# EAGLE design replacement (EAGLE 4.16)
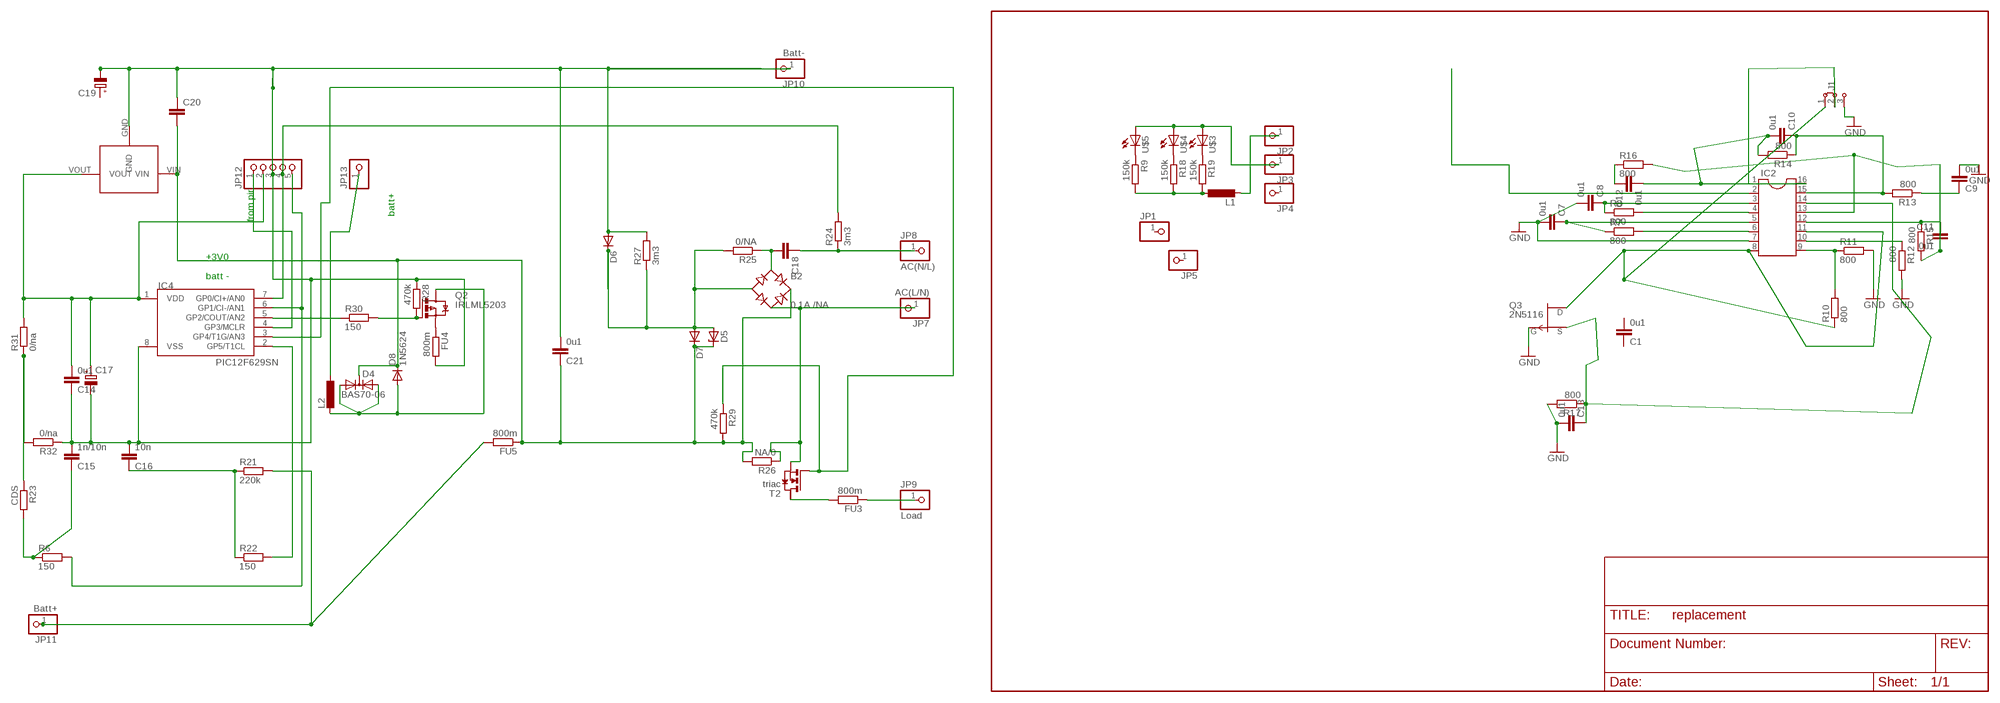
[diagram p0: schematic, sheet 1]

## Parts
B2  0.1A /NA  RECTIFIER-B40S  [B40S]
C1  0u1  C-EUC1206  [C1206]
C7  0u1  C-EUC1206  [C1206]
C8  0u1  C-EUC1206  [C1206]
C9  0u1  C-EUC1206  [C1206]
C10  0u1  C-EUC1206  [C1206]
C11  0u1  C-EUC1206  [C1206]
C12  0u1  C-EUC1206  [C1206]
C13  0u1  C-EUC1206  [C1206]
C14  0u1  C-EUC1206  [C1206]
C15  1n/10n  C-EUC1206  [C1206]
C16  10n  C-EUC1206  [C1206]
C17  CPOL-EUE2.5-6  [E2,5-6]
C18  C-EU050-025X075  [C050-025X075]
C19  CPOL-EUE2,5-6E  [E2,5-6E]
C20  C-EUC0805  [C0805]
C21  0u1  C-EUC1206  [C1206]
D4  BAS70-06  [SOT23]
D5  ZENER-DIODESOT23  [SOT23]
D6  DIODE-MELF-MLL41  [MELF-MLL41]
D7  DIODE-MINIMELF  [MINIMELF]
D8  1N5624  [DO201-15]
FU3  800m  R-EU_0204/5  [0204/5]
FU4  800m  R-EU_0204/5  [0204/5]
FU5  800m  R-EU_0204/5  [0204/5]
IC2  DIL16  [DIL16]
IC4  PIC12F629SN  [SO-08]
J1  J2X2MM  [04C]
JP1  PINHD-1X1  [1X01]
JP2  PINHD-1X1  [1X01]
JP3  PINHD-1X1  [1X01]
JP4  PINHD-1X1  [1X01]
JP5  PINHD-1X1  [1X01]
JP7  AC(L/N)  PINHD-1X1  [1X01]
JP8  AC(N/L)  PINHD-1X1  [1X01]
JP9  Load  PINHD-1X1  [1X01]
JP10  Batt-  PINHD-1X1  [1X01]
JP11  Batt+  PINHD-1X1  [1X01]
JP12  PINHD-1X5  [1X05]
JP13  PINHD-1X1  [1X01]
L1  L-EU0207/7  [0207/7]
L2  L-EU2200-15.24  [2200-15.24]
Q2  IRLML5203  [MICRO3]
Q3  2N5116  [TO18]
R6  150  R-EU_R0805  [R0805]
R7  800  R-EU_R1206  [R1206]
R8  800  R-EU_R1206  [R1206]
R9  150k  R-EU_R1206  [R1206]
R10  800  R-EU_R1206  [R1206]
R11  800  R-EU_R1206  [R1206]
R12  800  R-EU_R1206  [R1206]
R13  800  R-EU_R1206  [R1206]
R14  800  R-EU_R1206  [R1206]
R15  800  R-EU_R1206  [R1206]
R16  800  R-EU_R1206  [R1206]
R17  800  R-EU_R1206  [R1206]
R18  150k  R-EU_R1206  [R1206]
R19  150k  R-EU_R1206  [R1206]
R21  220k  R-EU_R0805  [R0805]
R22  150  R-EU_R0805  [R0805]
R23  CDS  R-EU_0411/3V  [0411V]
R24  3m3  R-EU_R1206  [R1206]
R25  0/NA  R-EU_R0402  [R0402]
R26  NA/0  R-EU_R0402  [R0402]
R27  3m3  R-EU_R1206  [R1206]
R28  470k  R-EU_R0805  [R0805]
R29  470k  R-EU_R0805  [R0805]
R30  150  R-EU_R0805  [R0805]
R31  0/na  R-EU_R0402  [R0402]
R32  0/na  R-EU_R0402  [R0402]
T2  triac  NMOSSOT223  [SOT223]
U$1  VREG-S  [TO92-S]
U$3  LED5MM  [LED5MM]
U$4  LED5MM  [LED5MM]
U$5  LED5MM  [LED5MM]

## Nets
GND: C7.2 C8.2 C9.2 C13.2 C14.1 C15.2 C16.2 C17.- C19.- C20.1 C21.2 D6.A FU4.2 IC2.7 IC4.8(VSS) J1.3 JP10.1 JP12.3 Q3.2(G) R11.2 R12.2 R17.2 R27.2 R28.1 R32.1 U$1.GND
N$8: C15.1 R6.1 R23.2
N$10: C16.1 R21.1 R22.1
N$11: JP2.1 L1.2
N$15: IC4.4(GP3/MCLR) JP12.1
N$17: IC2.2
N$19: D4.1(A1) D4.2(A2) D8.A L2.2 Q2.3(D)
N$20: C18.1 JP8.1 R24.1
N$21: FU3.1 JP9.1
N$22: FU3.2 T2.2(D)
N$24: B2.AC2 JP7.1 R26.1 T2.3(S)
N$25: B2.- D5.1(A) D6.C D7.A R25.2 R27.1
N$26: B2.AC1 C18.2 R25.1
N$27: IC4.7(GP0/CI+/AN0) JP12.4 R24.2
N$28: JP13.1 L2.1
N$31: FU4.1 Q2.2(S)
N$32: JP3.1 U$3.A U$4.A U$5.A
N$34: IC2.8 IC2.11 J1.1 Q3.3(D) R10.1
N$38: R9.1 U$5.K(C)
N$39: IC2.1 J1.2
N$40: C8.1 IC2.3 R8.1
N$41: IC2.6 R7.2
N$42: IC2.4 R8.2
N$43: C7.1 IC2.5 R7.1
N$44: IC2.10 R12.1
N$45: IC2.9 R10.2 R11.1
N$46: C9.1 R13.1
N$47: C10.1 IC2.15 R13.2 R14.1
N$48: C11.1 IC2.12 R15.1
N$49: C12.1 R16.1
N$50: C13.1 IC2.14 Q3.1(S) R17.1
N$51: C11.2 IC2.13 R15.2 R16.2
N$52: FU5.2 JP11.1 R21.2
N$53: C10.2 C12.2 IC2.16 R14.2
N$54: R18.1 U$4.K(C)
N$55: R19.1 U$3.K(C)
N$56: IC4.3(GP4/T1G/AN3) R29.1 T2.1(G)
N$58: L1.1 R9.2 R18.2 R19.2
N$59: Q2.1(G) R28.2 R30.2
N$60: IC4.5(GP2/COUT/AN2) R30.1
N$61: IC4.6(GP1/CI-/AN1) JP12.5 R6.2
N$62: IC4.2(GP5/T1CL) R22.2
N$63: R23.1 R31.1 R32.2
N$64: C14.2 C17.+ IC4.1(VDD) JP12.2 R31.2 U$1.VOUT
N$65: B2.+ C20.2 C21.1 D4.3(C) D5.3(C) D7.C D8.C FU5.1 R26.2 R29.2 U$1.VIN
Unconnected: C1.1 C1.2 C19.+ JP1.1 JP4.1 JP5.1 T2.4(D2)

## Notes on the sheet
- batt+
- from pir
- +3V0
- batt -

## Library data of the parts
B2 = rectifier:RECTIFIER-: Rectifier
C1 C7-C16 C18 C21 = rcl:C-EU: CAPACITOR, European symbol
C17 C19 = rcl(2):CPOL-EU: POLARIZED CAPACITOR, European symbol
C20 = rcl(2):C-EU: CAPACITOR, European symbol
D4 = diode-1:BAS70-06: Silicon Schottky Diodes General-purpose diode for high-speed switching
D5 = diode-1:ZENER-DIODE: Z-Diode
D6 D7 = diode-1:DIODE-: DIODE
D8 = diode:1N5624: DIODE
FU3-FU5 R6-R19 R21-R32 = rcl:R-EU_: RESISTOR, European symbol
IC2 = ic-package:DIL16: Dual In Line
IC4 = microchip-3:PIC12F6*: uPC nW 1k Program Flash memory 2x Timer Comparator 10b A/D converter/ 4xIN
J1 = jumper:J2: Jumper switch 2 x 2.5 mm
JP1-JP5 JP7-JP11 = pinhead:PINHD-1X1: PIN HEADER
JP12 = pinhead(2):PINHD-1X5: PIN HEADER
JP13 = pinhead(2):PINHD-1X1: PIN HEADER
L1 L2 = rcl:L-EU: INDUCTOR, European symbol
Q2 = transistor-power:IRLML5203: HEXFET P-Channel Power MOSFET
Q3 = transistor-fet:2N5116: P-Channel Junction FET Source: Vishay 70260.pdf
T2 = zetex:NMOSSOT223: MOS FET
U$1 = spoton:VREG-S: vreg aus spoton
U$3-U$5 = led(3):LED: LED

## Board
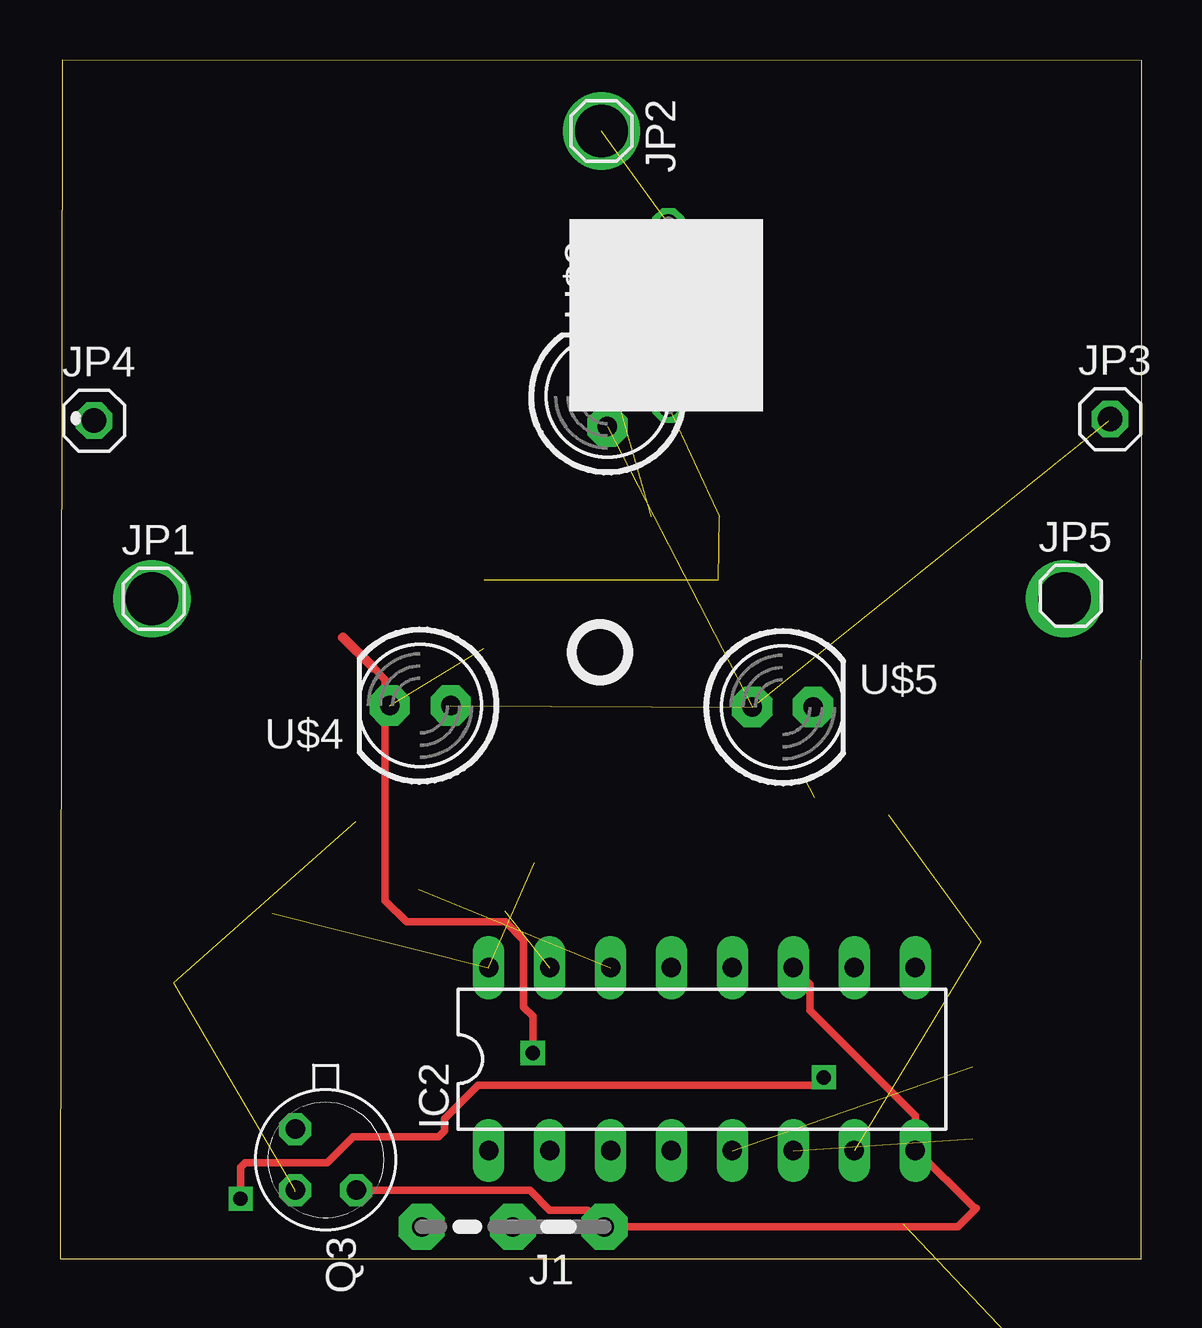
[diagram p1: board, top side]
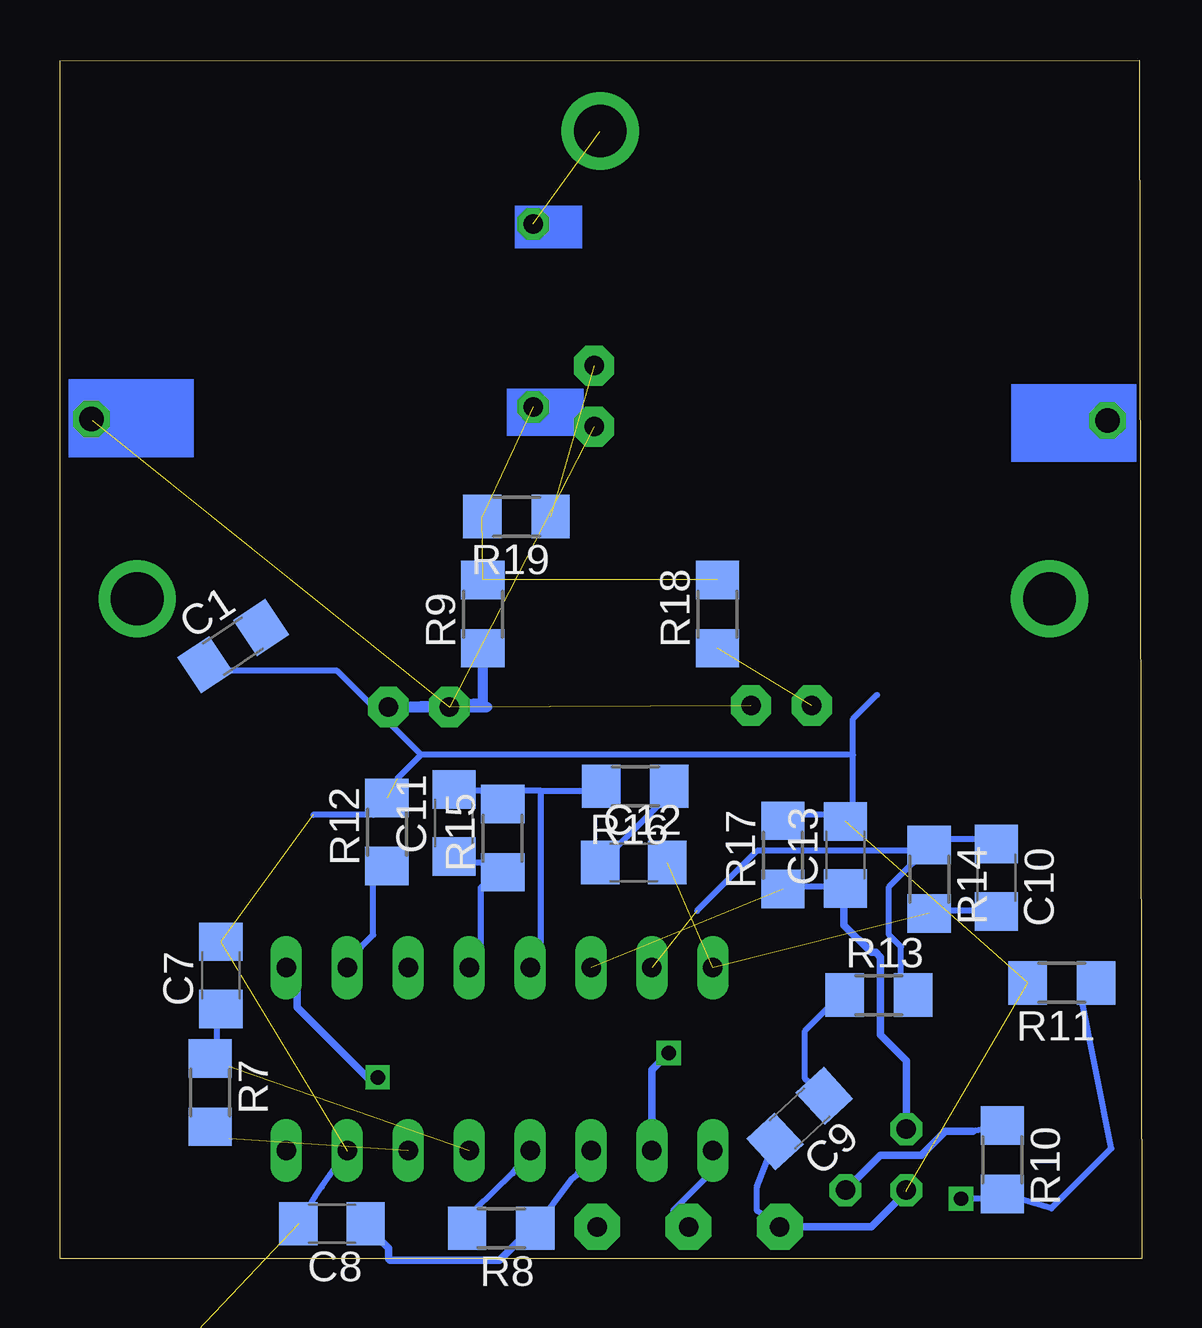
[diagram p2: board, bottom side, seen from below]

Size 45.09 x 49.94 mm. Coordinates in mm from the lower left corner, seen from the top.
Outline: 0,0 45.07,0 45.08,49.91 0.09,49.94 0,0
Copper layers (1*16): Top 0.035mm / dielectric 1.5mm / Bottom 0.035mm
Design rules "default": minimum track width 10mil, minimum drill 24mil, track to track 8mil, track to pad 8mil, pad to pad 8mil, via to via 8mil, smd to smd 8mil, copper to edge 40mil, drill to drill 8mil, minimum pad ring 10mil, minimum via ring 8mil, stop-mask expansion 4mil, vias tented up to drill 0mil, thermal gap 10mil

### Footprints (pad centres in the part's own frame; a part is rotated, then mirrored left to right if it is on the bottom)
B40S = smd 1.5 x 1.7: + -2.55,-4.5; - 2.55,-4.5; AC1 -2.55,4.5; AC2 2.55,4.5
C1206 = smd 1.6 x 1.8: 1 -1.4,0; 2 1.4,0
E2,5-6 = drill 0.813 pad 1.6 round: + -1.27,0 | drill 0.813 pad 1.6 octagon: - 1.27,0
C050-025X075 = drill 0.813 octagon: 1 -2.54,0; 2 2.54,0
E2,5-6E = drill 0.813 pad 1.575 round: + -1.27,0 | drill 0.813 pad 1.575 octagon: - 1.27,0
C0805 = smd 1.3 x 1.5: 1 -0.95,0; 2 0.95,0
SOT23 = smd 1 x 1.4: 1 -0.95,-1.1; 2 0.95,-1.1; 3 0,1.1
MELF-MLL41 = smd 2.5 x 3: A 2.625,0; C -2.625,0
MINIMELF = smd 1.4 x 1.8: A 1.7,0; C -1.7,0
DO201-15 = drill 1.499 long: A 7.62,0; C -7.62,0
0204/5 = drill 0.813 octagon: 1 -2.54,0; 2 2.54,0
DIL16 = drill 0.813 long: 1 -8.89,-3.81; 2 -6.35,-3.81; 3 -3.81,-3.81; 4 -1.27,-3.81; 5 1.27,-3.81; 6 3.81,-3.81; 7 6.35,-3.81; 8 8.89,-3.81; 9 8.89,3.81; 10 6.35,3.81; 11 3.81,3.81; 12 1.27,3.81; 13 -1.27,3.81; 14 -3.81,3.81; 15 -6.35,3.81; 16 -8.89,3.81
SO-08 = smd 0.6 x 2.2: 1 -1.905,-2.6; 2 -0.635,-2.6; 3 0.635,-2.6; 4 1.905,-2.6; 5 1.905,2.6; 6 0.635,2.6; 7 -0.635,2.6; 8 -1.905,2.6
04C = drill 0.813 pad 1.905 octagon: 1 -1.905,0; 2 1.905,0; 3 5.715,0
1X01 = drill 1.016 octagon: 1 0,0
1X05 = drill 1.016 square: 1 -5.08,0 | drill 1.016 octagon: 2 -2.54,0; 3 0,0; 4 2.54,0; 5 5.08,0
1X01' = drill 1.016 square: 1 0,0
0207/7 = drill 0.813 octagon: 1 -3.81,0; 2 3.81,0
2200-15.24 = drill 0.8 pad 1.27 round: 1 -7.62,0; 2 7.62,0
MICRO3 = smd 0.8 x 0.9: 1 -0.95,-1; 2 0.95,-1; 3 0,1
TO18 = drill 0.813 octagon: 1 -1.27,-1.27; 2 1.27,-1.27; 3 1.27,1.27
R0805 = smd 1.3 x 1.5: 1 -0.85,0; 2 0.85,0
R1206 = smd 1.6 x 1.803: 1 -1.422,0; 2 1.422,0
0411V = drill 0.914 octagon: 1 -2.54,0; 2 1.27,0
R0402 = smd 0.7 x 0.9: 1 -0.65,0; 2 0.65,0
SOT223 = smd 1.219 x 2.235: 1 -2.311,-3.099; 2 0,-3.099; 3 2.311,-3.099 | smd 3.6 x 2.2: 4 0,3.099
TO92-S = drill 0.6 round: GND -2.54,0; VOUT 0,0 | drill 0.6 offset: VIN -1.27,1.27
LED5MM = drill 0.813 pad 1.676 octagon: A -1.27,0; K 1.27,0

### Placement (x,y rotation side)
B2  not placed on the board
C1  37.87,25.52 33.7 bottom
C7  38.38,11.81 90 bottom
C8  33.74,1.46 180 bottom
C9  14.25,5.84 222.8 bottom
C10  6.06,15.87 270 bottom
C11  28.66,18.16 90 bottom
C12  21.17,16.51 0 bottom
C13  12.34,16.82 90 bottom
C14  not placed on the board
C15  not placed on the board
C16  not placed on the board
C17  not placed on the board
C18  not placed on the board
C19  not placed on the board
C20  not placed on the board
C21  not placed on the board
D4  not placed on the board
D5  not placed on the board
D6  not placed on the board
D7  not placed on the board
D8  not placed on the board
FU3  not placed on the board
FU4  not placed on the board
FU5  not placed on the board
IC2  26.76,8.31 0 top
IC4  not placed on the board
J1  20.79,1.33 180 top
JP1  3.9,27.49 0 top
JP2  22.57,46.98 270 top
JP3  43.78,34.98 0 top
JP4  1.42,34.92 0 top
JP5  42.13,27.62 0 top
JP7  not placed on the board
JP8  not placed on the board
JP9  not placed on the board
JP10  not placed on the board
JP11  not placed on the board
JP12  not placed on the board
JP13  [1X01']  not placed on the board
L1  25.36,39.3 90 top
L2  not placed on the board
Q2  not placed on the board
Q3  11.07,4.12 270 top
R6  not placed on the board
R7  38.82,6.92 270 bottom
R8  26.7,1.27 180 bottom
R9  27.46,26.86 90 bottom
R10  5.8,4.12 270 bottom
R11  3.33,11.49 180 bottom
R12  31.46,17.78 90 bottom
R13  10.95,10.98 0 bottom
R14  8.85,15.81 270 bottom
R15  26.63,17.52 90 bottom
R16  21.11,19.68 180 bottom
R17  14.95,16.82 90 bottom
R18  17.68,26.86 90 bottom
R19  26.06,30.92 180 bottom
R21  not placed on the board
R22  not placed on the board
R23  not placed on the board
R24  not placed on the board
R25  not placed on the board
R26  not placed on the board
R27  not placed on the board
R28  not placed on the board
R29  not placed on the board
R30  not placed on the board
R31  not placed on the board
R32  not placed on the board
T2  not placed on the board
U$1  not placed on the board
U$3  22.82,35.94 90 top
U$4  15.01,23.05 180 top
U$5  30.12,22.98 0 top

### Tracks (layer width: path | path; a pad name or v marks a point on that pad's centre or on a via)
GND  (22 unrouted)
  Bottom 0.254: R17.2 14.53,18.5 13.03,18.5 C13.2 12.03,19 12.03,21 | 12.03,21 12.03,22.5 11.03,23.5 | 30.03,21 31.03,20 | 12.03,21 30.03,21 | 38.03,24.5 33.53,24.5 30.03,21 | 34.53,18.5 32.03,18.5 R12.2 | C9.2 16.03,3 16.03,2 J1.3 | C8.2 34.43,2.61 34.18,2.99 IC2.7
  Bottom 0.305: J1.3 11.26,1.33 9.8,2.79
N$2  (via drill 2.2)
  other vias: 3.84,27.49
N$3  (via drill 2.2)
  other vias: 41.87,27.49
N$5  (via drill 2.2)
  other vias: 22.57,46.98
N$8  (2 unrouted)
N$10  (2 unrouted)
N$11  (1 unrouted)
N$15  (1 unrouted)
N$17  (via drill 0.6)
  Top 0.305: v19.71,8.57 19.71,10.09 19.33,10.47 19.33,13.27 18.57,14.03 14.44,14.03 13.55,14.92 13.55,24.12 13.04,24.63
  Top 0.406: 13.04,24.63 11.79,25.89
  Bottom 0.305: IC2.2 20.41,7.87 v19.71,8.57
N$19  (4 unrouted)
N$20  (2 unrouted)
N$21  (1 unrouted)
N$22  (1 unrouted)
N$24  (3 unrouted)
N$25  (5 unrouted)
N$26  (2 unrouted)
N$27  (2 unrouted)
N$28  (1 unrouted)
N$31  (1 unrouted)
N$32  (3 unrouted)
  Bottom 0.406: JP3.1 43.71,34.92
N$34
  Top 0.305: Q3.3 19.58,2.85 20.41,2.03 22,2.03 J1.1 37.43,1.33 38.19,2.09 38.13,2.09 35.65,4.57 | 35.65,4.57 35.59,4.63 | 35.65,4.57 IC2.8 35.65,5.96 31.27,10.35 31.27,11.42 IC2.11 30.51,12.19
  Bottom 0.254: R10.1 7.03,5.31
  Bottom 0.305: 7.03,5.31 8.17,5.31 9.17,4.31 10.88,4.31 Q3.3
N$38
  Bottom 0.406: 27.27,22.98 U$5.K 27.46,23.17 R9.1
N$39
  Bottom 0.254: IC2.1 18.03,3.5 19.53,2 J1.2
N$40
  Bottom 0.254: R8.1 23.77,3.3 23.53,3.5 IC2.3
  Bottom 0.305: R8.1 25.43,1.27 26.76,-0.07 31.33,-0.07 31.39,-0.01 31.39,0.44 32.41,1.46 | 32.41,1.46 32.47,1.52 | 32.41,1.46 C8.1
N$41  (1 unrouted)
  Bottom 0.254: 38.03,5 R7.2
N$42
  Bottom 0.254: R8.2 27.79,2.03 26.22,3.56 IC2.4
N$43  (1 unrouted)
  Bottom 0.254: C7.1 38.53,9.99 38.53,8.99 R7.1 38.03,8
N$44
  Bottom 0.254: R12.1 32.03,15.99 32.03,13.49 32.53,12.99 IC2.10
N$45  (via drill 0.6)
  Top 0.305: v7.53,2.5 7.53,3.81 7.71,4 11.14,4 12.22,5.08 15.77,5.08 16.03,5.33 16.03,5.84 17.42,7.23 31.52,7.23 v31.84,7.55
  Bottom 0.254: R11.1 2.53,10.99 1.26,4.6 3.76,2.1 R10.2 6.53,2.5 v7.53,2.5
  Bottom 0.305: v31.84,7.55 32.28,7.55 35.2,10.47 35.2,11.68 IC2.9
N$46
  Bottom 0.254: C9.1 14.03,7.5 14.03,9.49 13.03,10.49 R13.1
N$47  (1 unrouted)
  Bottom 0.254: C10.1 6.53,17.5 8.03,17.5 R14.1 | R13.2 10.03,11.49 10.03,12.99 10.53,13.49 10.53,15.49 9.53,16.5 R14.1 | 18.53,14.49 16.03,17 9.53,17 R14.1
N$48
  Bottom 0.254: C11.1 28.03,16.5 27.53,16.5 R15.1 27.53,15.49 27.53,12.99 IC2.12
N$49
  Bottom 0.254: C12.1 22.03,17 20.03,19 R16.1
N$50  (1 unrouted)
  Bottom 0.254: C13.1 13.03,15.49 14.53,15.49 R17.1
  Bottom 0.305: Q3.1 9.8,8.25 10.88,9.33 10.88,12.57 11.07,12.76 11.26,12.76 12.41,13.9 12.41,15.04 12.15,15.3 12.28,15.42 C13.1
N$51
  Bottom 0.254: C11.2 28.03,19.5 27.53,19.5 R15.2 26.03,19.5 25.03,19.5 | 25.03,19.5 23.03,19.5 R16.2 | 25.03,19.5 25.03,12.99 IC2.13
N$52  (2 unrouted)
N$53  (2 unrouted)
  Bottom 0.254: R14.2 8.03,14.49 6.53,14.49 C10.2 6.53,13.99
N$54  (1 unrouted)
N$55  (1 unrouted)
N$56  (2 unrouted)
N$58  (3 unrouted)
N$59  (2 unrouted)
N$60  (1 unrouted)
N$61  (2 unrouted)
N$62  (1 unrouted)
N$63  (2 unrouted)
N$64  (5 unrouted)
N$65  (10 unrouted)
(copper drawn outside any net)
  shapes: Bottom area x4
